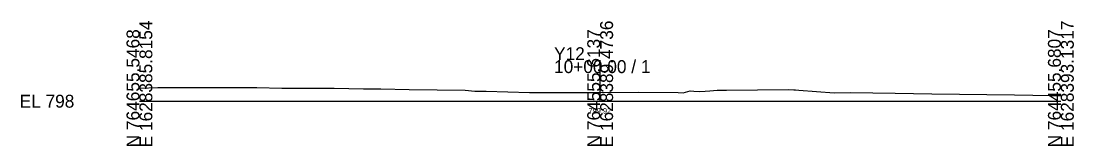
# Model space of a CAD drawing. Extents: x -26 to 203, y -10 to 3521.
# Drawn here: x -25.7 to 202.8, y -9.7 to 17.4 of the extents above; entities that cross this region are included whole.
import ezdxf

# ---------------------------------------------------------------- set-up
doc = ezdxf.new("R2010")
doc.units = 0
for name, color, linetype in [('Default', 7, 'Continuous'), ('Exist Cross Section Cell', 7, 'Continuous'), ('Exist XS Center Line Elevation Label', 7, 'Continuous'), ('Exist XS Ground Line', 7, 'Continuous')]:
    doc.layers.add(name, color=color, linetype=linetype)

msp = doc.modelspace()

# ---------------------------------------------------------------- linework, layer by layer
at = {"layer": 'Exist Cross Section Cell'}
for p, q in [((100, 0), (100, 8.9)), ((0, 0), (100, 0)), ((100, 0), (200, 0))]:
    msp.add_line(p, q, dxfattribs=at)
at = {"layer": 'Exist XS Ground Line'}
msp.add_lwpolyline([(0, 2.85), (4.01, 2.97), (25.45, 2.95), (30.91, 2.82), (39.04, 2.81), (39.69, 2.83), (42.26, 2.8), (48.64, 2.72), (52.39, 2.66), (58.52, 2.51), (70.73, 2.36), (72.82, 2.2), (75.25, 2.21), (84.66, 1.87), (85.1, 1.87), (90.62, 1.88), (100, 1.92), (108.29, 1.95), (116.93, 1.91), (117.99, 1.79), (119.01, 2.13), (119.55, 2.23), (120.3, 2.2), (121.56, 2.13), (122.78, 2.16), (123.8, 2.23), (124.6, 2.34), (125.39, 2.42), (126.46, 2.42), (127.45, 2.42), (140.89, 2.51), (142.01, 2.49), (142.41, 2.44), (143.1, 2.43), (150.78, 1.85), (154.32, 1.87), (164.06, 1.76), (172.01, 1.62), (189.95, 1.41), (197.92, 1.25), (200, 1.22)], dxfattribs=at)

# ---------------------------------------------------------------- texts
at = {"layer": 'Default'}
msp.add_text('-', height=0.0001, dxfattribs=at).set_placement((0, 0))
at = {"layer": 'Exist Cross Section Cell'}
for s, p in [('E 1628385.8154', (2.8, -10)), ('E 1628389.4736', (102.8, -10)), ('E 1628393.1317', (202.8, -10)), ('N 764655.5468', (0, -10)), ('N 764555.6137', (100, -10)), ('N 764455.6807', (200, -10))]:
    msp.add_text(s, height=2.8, rotation=90, dxfattribs=at).set_placement(p)
for s, p in [('Y12', (90, 8.9)), ('10+00.00 / 1', (90, 6.1)), ('EL 798', (-26, -1.4))]:
    msp.add_text(s, height=2.8, dxfattribs=at).set_placement(p)
at = {"layer": 'Exist XS Center Line Elevation Label'}
msp.add_text('799.92', height=1.2, dxfattribs=at).set_placement((97.48, -2.68))

doc.saveas('drawing.dxf')
